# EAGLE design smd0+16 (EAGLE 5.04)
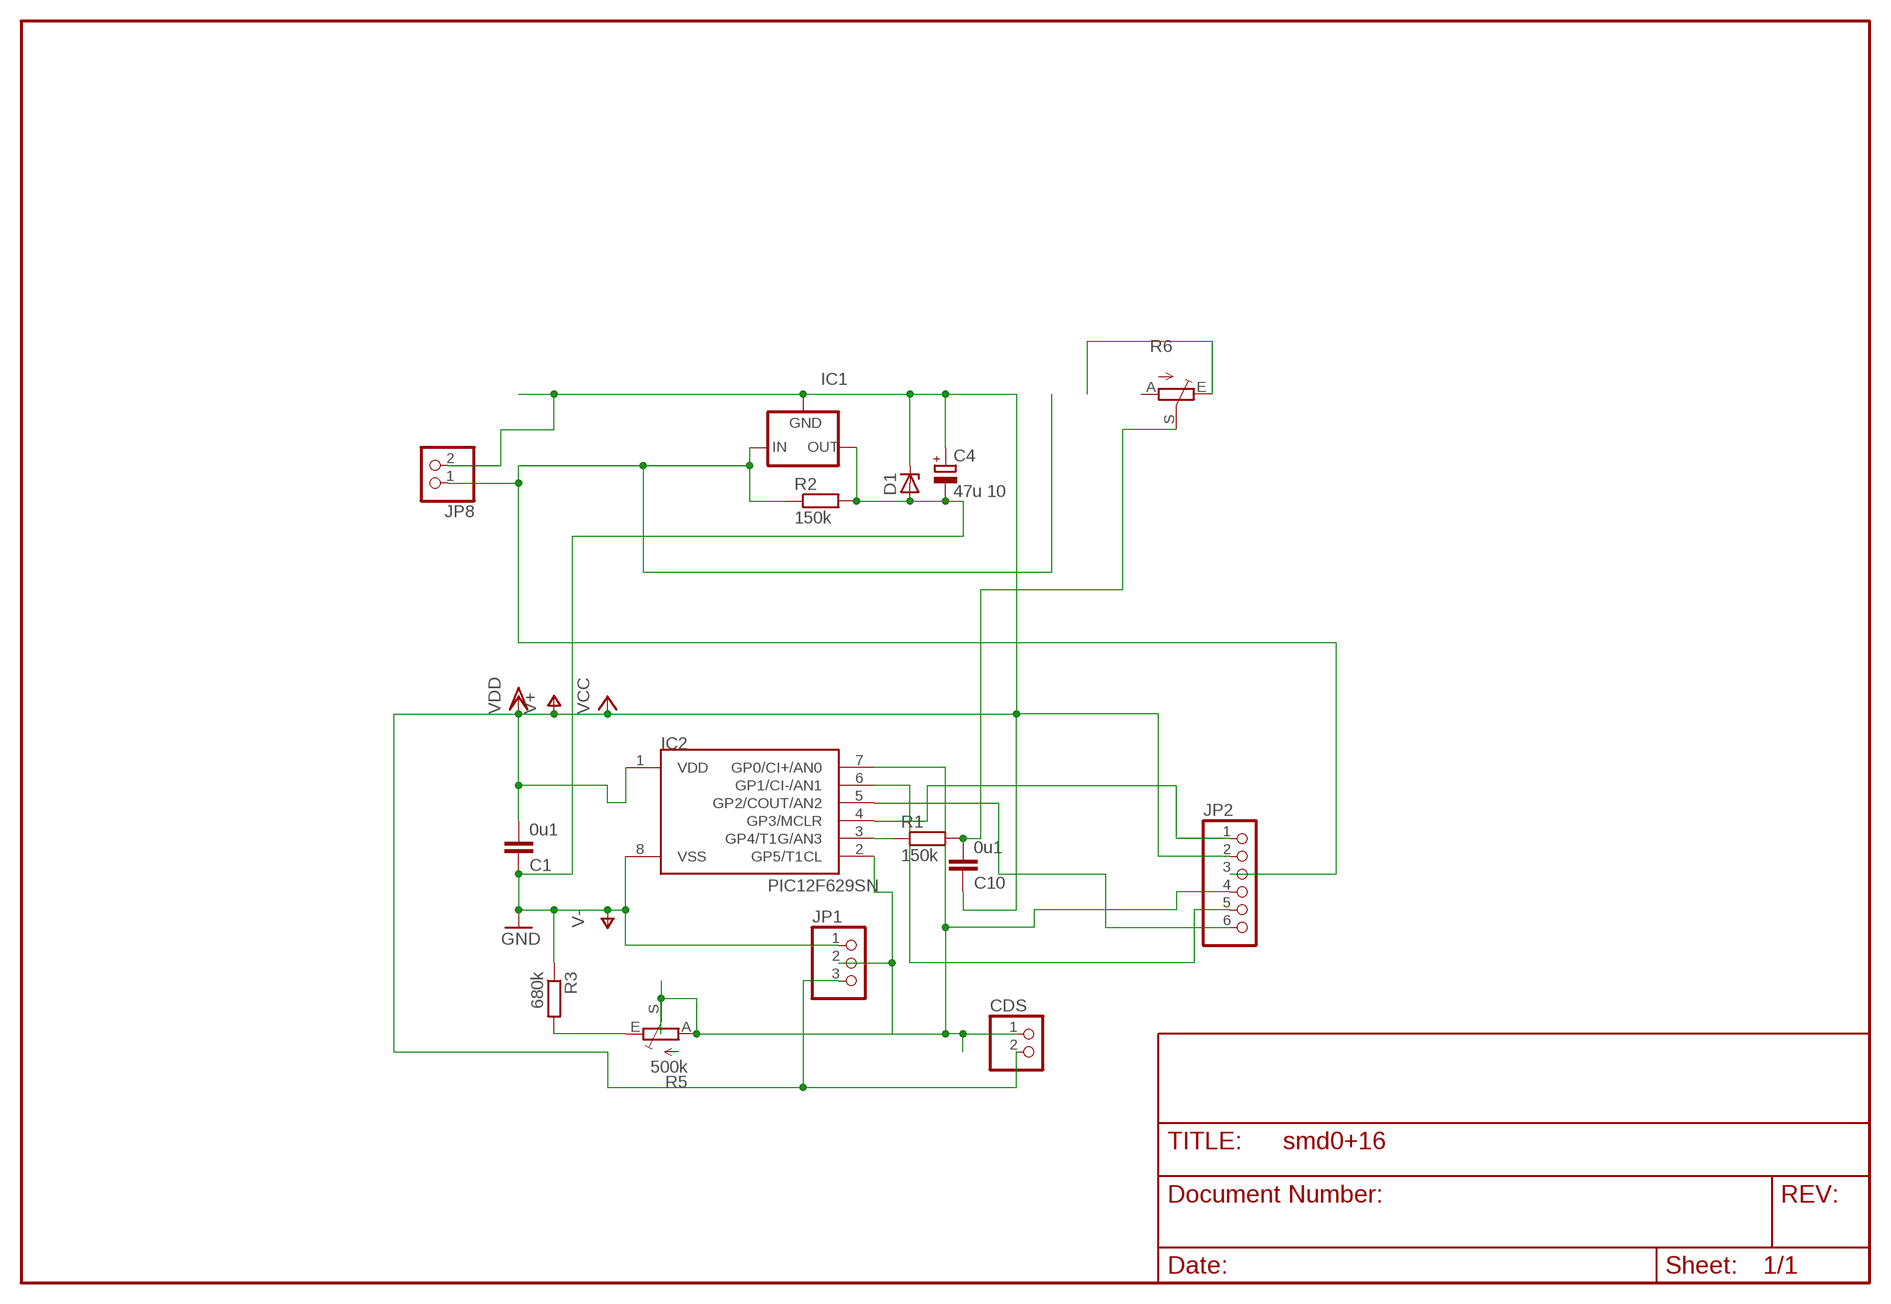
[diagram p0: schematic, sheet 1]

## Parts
C1  0u1  C-EUC1206  [C1206]
C4  47u 10  CPOL-EUE2.5-6  [E2,5-6]
C10  0u1  C-EUC1206  [C1206]
CDS  PINHD-1X2  [1X02]
D1  ZENER-DIODESOT23  [SOT23]
IC1  79LXX  [79LXX]
IC2  PIC12F629SN  [SO-08]
JP1  PINHD-1X3  [1X03]
JP2  PINHD-1X6  [1X06]
JP8  PINHD-1X2  [1X02]
R1  150k  R-EU_R0805  [R0805]
R2  150k  R-EU_0204/2V  [0204V]
R3  680k  R-EU_R1206  [R1206]
R5  500k  TRIM_EU-CA6V  [CA6V]
R6  TRIM_EU-CA6V  [CA6V]

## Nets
CDS: IC2.2(GP5/T1CL) JP1.2
N$1: C10.2 R1.2 R6.S
N$2: IC2.5(GP2/COUT/AN2) JP2.6
N$3: IC2.4(GP3/MCLR) JP2.1
N$4: CDS.1 IC2.7(GP0/CI+/AN0) JP2.4 R5.A R5.S
N$5: R3.2 R5.E
N$7: R6.E
N$8: IC2.3(GP4/T1G/AN3) R1.1
N$10: IC1.IN JP2.3 JP8.1 R2.1
N$15: IC2.6(GP1/CI-/AN1) JP2.5
V+: C1.2 C4.+ C10.1 CDS.2 D1.3(C) IC1.GND IC2.1(VDD) JP1.3 JP2.2 JP8.2 ; supply symbol labelled VCC, VDD
V-: C1.1 C4.- D1.1(A) IC1.OUT IC2.8(VSS) JP1.1 R2.2 R3.1 ; supply symbol labelled GND
Unconnected: R6.A

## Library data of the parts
C1 C10 = rcl:C-EU: CAPACITOR, European symbol
C4 = rcl:CPOL-EU: POLARIZED CAPACITOR, European symbol
CDS JP8 = pinhead:PINHD-1X2: PIN HEADER
D1 = diode-1:ZENER-DIODE: Z-Diode
IC1 = v-reg:79LXX: VOLTAGE REGULATOR
IC2 = microchip-3:PIC12F6*: uPC nW 1k Program Flash memory 2x Timer Comparator 10b A/D converter/ 4xIN
JP1 = pinhead(2):PINHD-1X3: PIN HEADER
JP2 = pinhead:PINHD-1X6: PIN HEADER
R1-R3 = rcl:R-EU_: RESISTOR, European symbol
R5 R6 = pot:TRIM_EU-: POTENTIOMETER

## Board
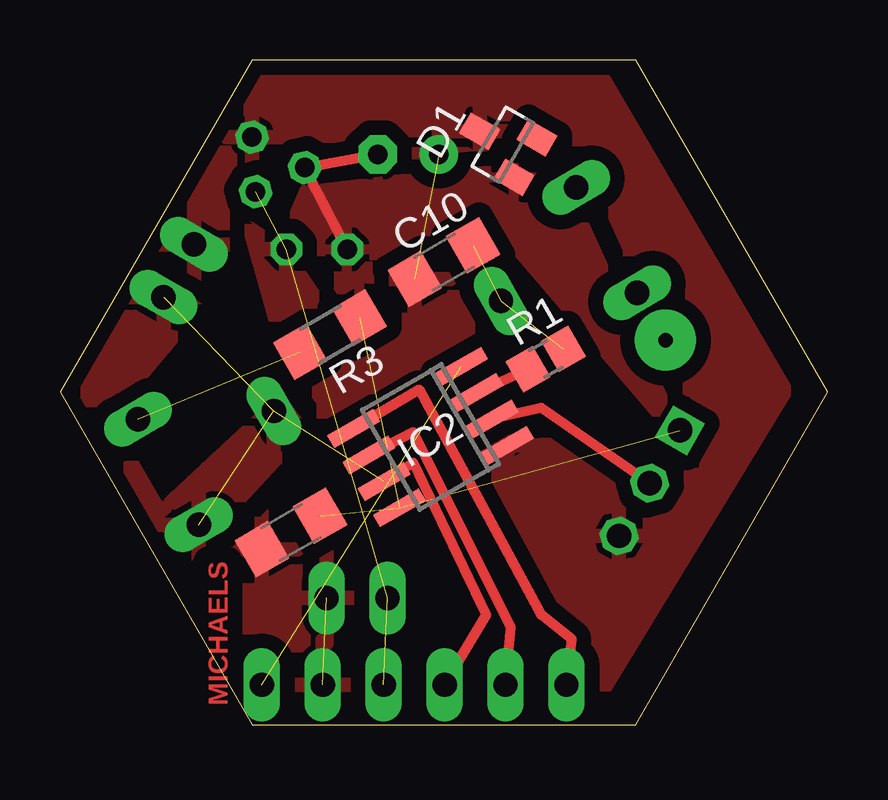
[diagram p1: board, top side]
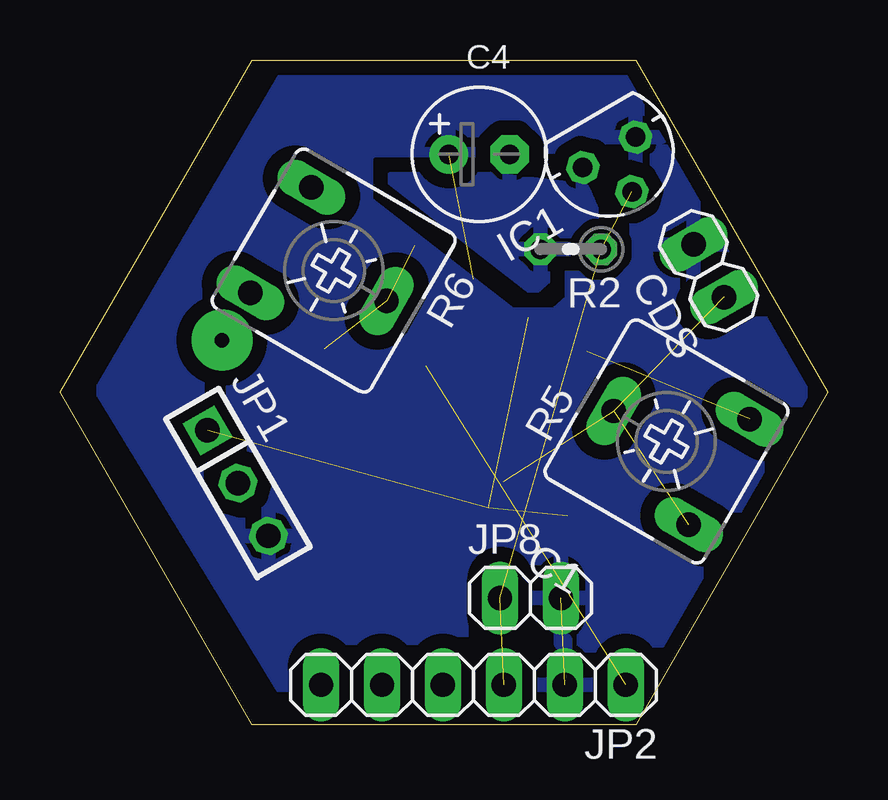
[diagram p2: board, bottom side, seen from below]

Size 32 x 27.71 mm. Coordinates in mm from the lower left corner, seen from the top.
Outline: 8,0 24,0 32,13.86 24,27.71 8,27.71 0,13.86 8,0
Copper layers (1*16): Top 0.035mm / dielectric 1.5mm / Bottom 0.035mm
Design rules "default *": minimum track width 10mil, minimum drill 24mil, track to track 8mil, track to pad 8mil, pad to pad 8mil, via to via 8mil, smd to smd 8mil, copper to edge 10mil, drill to drill 8mil, minimum pad ring 10mil, minimum via ring 8mil, stop-mask expansion 4mil, vias tented up to drill 0mil, thermal gap 10mil

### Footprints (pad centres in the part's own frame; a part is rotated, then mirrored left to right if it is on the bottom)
C1206 = smd 1.6 x 1.8: 1 -1.4,0; 2 1.4,0
E2,5-6 = drill 0.813 pad 1.6 round: + -1.27,0 | drill 0.813 pad 1.6 octagon: - 1.27,0
1X02 = drill 1.016 long: 1 -1.27,0; 2 1.27,0
SOT23 = smd 1 x 1.4: 1 -0.95,-1.1; 2 0.95,-1.1; 3 0,1.1
79LXX = drill 0.813 octagon: GND -1.27,0; IN 0,1.905; OUT 1.27,0
SO-08 = smd 0.6 x 2.2: 1 -1.905,-2.6; 2 -0.635,-2.6; 3 0.635,-2.6; 4 1.905,-2.6; 5 1.905,2.6; 6 0.635,2.6; 7 -0.635,2.6; 8 -1.905,2.6
1X03 = drill 1.016 square: 1 -2.54,0 | drill 1.016 octagon: 2 0,0; 3 2.54,0
1X06 = drill 1.016 long: 1 -6.35,0; 2 -3.81,0; 3 -1.27,0; 4 1.27,0; 5 3.81,0; 6 6.35,0
R0805 = smd 1.3 x 1.5: 1 -0.85,0; 2 0.85,0
0204V = drill 0.813 octagon: 1 -1.27,0; 2 1.27,0
R1206 = smd 1.6 x 1.803: 1 -1.422,0; 2 1.422,0
CA6V = drill 1.016 long: A -2.54,-2.54; E 2.54,-2.54; S 0,2.54

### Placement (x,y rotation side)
C1  9.63,8.01 210 top
C4  14.52,23.78 0 bottom
C10  16,19.28 30 top
CDS  4.95,18.92 120 bottom
D1  18.45,24.19 60 top
IC1  9.1,23.86 210 bottom
IC2  15.45,11.99 120 top
JP1  24.58,10.07 300 bottom
JP2  14.77,1.66 180 bottom
JP8  12.38,5.27 0 bottom
R1  20.25,15.24 30 top
R2  10.71,19.82 180 bottom
R3  11.25,16.26 210 top
R5  6.71,11.8 60 bottom
R6  20.59,18.93 240 bottom

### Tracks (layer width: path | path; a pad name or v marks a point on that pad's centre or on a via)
CDS
  Top 0.406: IC2.2 20.07,13.21 JP1.2
N$1  (2 unrouted)
N$2
  Top 0.406: IC2.5 14.99,13.97 20.07,4.57 21.34,3.56 JP2.6
N$3  (1 unrouted)
N$4  (3 unrouted)
  Top 0.406: IC2.7 14.73,10.92 17.78,4.57 JP2.4
  pour Top (isolate 0.61): 2.42,18.98 -0.99,13.2 3.81,5.41 10.11,12.27 9.13,13.46 4.17,8.84 1.88,12.8 5.71,17.36
N$5  (1 unrouted)
N$8
  Top 0.406: IC2.3 R1.1
N$10  (3 unrouted)
  pour Top (isolate 0.61): 7.9,20.67 9.32,19.73 11.32,16.78 9.05,16.65
N$11  (via drill 0.6 pad 2.54)
  other vias: 25.25,16.03
N$15
  Top 0.406: IC2.6 14.73,12.19 18.8,4.06 JP2.5
V+  (2 unrouted)
  pour Bottom (isolate 0.61, rank 6): 0.46,13.74 8.08,0.54 22.29,0.83 30.14,14.16 8.34,28.01 6.7,27.32
  pour Bottom (isolate 0.61, rank 6): -0.95,13.34 8.08,0.54 22.29,0.83 30.26,13.94 22.21,27.68 6.65,27.2
  pour Top (isolate 0.61, rank 6): -0.95,13.34 8.08,0.54 22.29,0.83 30.26,13.94 22.21,27.68 6.65,27.2
V-  (3 unrouted)
  Top 0.406: C4.- IC1.OUT R2.2
  pour Top (isolate 0.61, rank 2): 10.19,22.29 14.03,22.75 20.71,23.38 26.08,11.52 18.86,19.97 12.07,17.51 9.69,21.12
  pour Bottom (isolate 0.61, rank 2): 10.19,22.29 14.03,22.75 18.13,22.77 12.26,18.2 10.45,19.8 9.69,21.12

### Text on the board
Top: MICHAELS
